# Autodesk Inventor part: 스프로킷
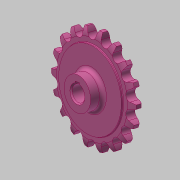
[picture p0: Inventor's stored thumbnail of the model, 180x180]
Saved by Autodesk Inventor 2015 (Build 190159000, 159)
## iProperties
Created: 2016-03
Part Number: 스프로킷
Material: 강철, 탄소
Document SubType Name: Modeling
Designer: mduedu
Density: 7.87 g/cm^3
Mass: 301.818 g
Surface Area: 124.882 cm^2
Volume: 38.3505 cm^3
Appearance: 분홍색
Author: mduedu
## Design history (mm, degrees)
sketch "스케치1"
  geometry: L1 (0, 5)-(29.5, 5); L2 (29.5, 5)-(29.5, 4.1); L3 (30, 3.6)-(33.625, 3.6); L4 (40, 2)-(40, 0); L5 (40, 0)-(0, 0); L6 (0, 0)-(0, 5); L7 (0, -5)-(29.5, -5); L8 (29.5, -5)-(29.5, -4.1); L9 (30, -3.6)-(33.625, -3.6); L10 (40, -2)-(40, 0); L11 (0, 0)-(0, -5); A1 r 13.5 centre (33.625, -9.9) between (40, 2) and (33.625, 3.6); A2 r 13.5 centre (33.625, 9.9) between (33.625, -3.6) and (40, -2); A3 r 0.5 centre (30, 4.1) between (29.5, 4.1) and (30, 3.6); A4 r 0.5 centre (30, -4.1) between (30, -3.6) and (29.5, -4.1); 2 further points
  constraints: 22 end point, 8 point on circle, 6 symmetric about line, 5 tangent, 4 centre point, 4 parallel, 4 point on line, 1 equal radius, 1 horizontal, 1 perpendicular, 1 other
  dimensions: "d0" = 80 diameter of L4 L6; "d2" = 59 diameter of L2 L6; "d3" = 1.6 vertical distance of L4.start L3.end; "d4" = 3.6 distance from line of L4.end L3; "d5" = 5 distance between parallel lines of L5 L1; "d6" = 13.5 radius of A1; "d15" = 0.5 radius of A3
revolve "회전1" sketch "스케치1" stored, may be unused: angle "d7" = 90 deg
sketch "스케치2" dims "d8" = 65.2, "d11" = 80
  geometry: L1 (0, 0)-(0, 32.6); A1 r 36.57 centre (0, 0) between (-16.231, 32.771) and (0, 36.57); A2 r 3.97 centre (0, 36.57) between (-3.866, 35.665) and (0, 32.6); A3 r 12.7 centre (-16.231, 32.771) between (-3.866, 35.665) and (-5.534, 39.615); A4 r 12.7 centre (16.231, 32.771) between (5.534, 39.615) and (3.866, 35.665); A5 r 3.97 centre (0, 36.57) between (0, 32.6) and (3.866, 35.665); A6 r 40 centre (0, 0) between (5.534, 39.615) and (-5.534, 39.615); 2 further points
  constraints: 12 point on circle, 6 centre point, 4 coincident, 3 symmetric about line, 2 end point, 1 point on line, 1 tangent, 1 vertical, 1 vertical alignment, 7 other
  dimensions: "d10" = 73.14 diameter of A1; "d12" = 12.7 radius of A3
extrude "돌출1" cut sketch "스케치2" stored distance "d13" = 10; taper "d14" = 0 deg
sketch "스케치3"
  geometry: C1 r 12.5 at (0, 0); 1 further point
  constraints: 1 centre point, 1 coincident
  dimensions: "d19" = 25 diameter of C1
extrude "돌출2" join sketch "스케치3" distance "d20" = 10; taper "d21" = 0 deg
fillet "모깎기1" dims "d22" = 3
sketch "스케치4"
  geometry: L1 (-2, 0)-(2, 0); L2 (2, 0)-(2, 7.8); L3 (2, 7.8)-(-2, 7.8); L4 (-2, 7.8)-(-2, 0); C1 r 6 at (0, 0); 2 further points
  constraints: 8 end point, 2 coincident, 2 parallel, 1 centre point, 1 horizontal, 1 midpoint, 1 perpendicular
  dimensions: "d23" = 12 diameter of C1; "d25" = 4 distance of L2.end L3.end; "d26" = 7.8 distance of L1.end L2.end
extrude "돌출3" cut sketch "스케치4" stored distance "d27" = 8; taper "d28" = 0 deg
chamfer "모따기2" distance "d42" = 1; stored, may be unused: second distance "d43" = 2, angle "d44" = 45 deg
node "솔리드1"
pattern_circular "원형 패턴1" dims angle "d17" = 360 deg
